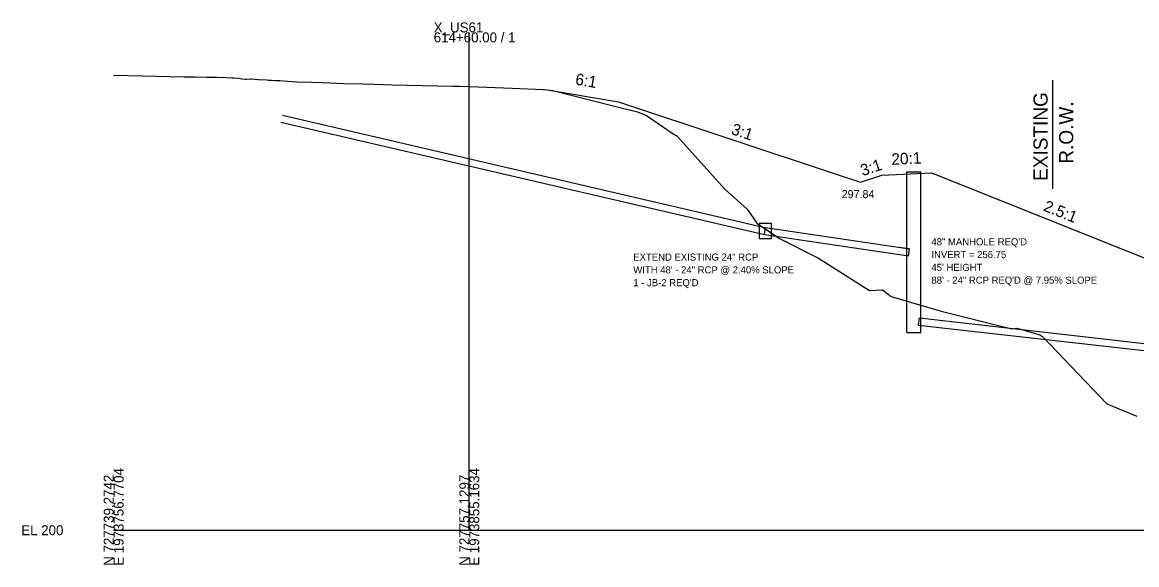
# Model space of a CAD drawing. Extents: x -26 to 1604, y -13 to 9623.
# Drawn here: x -25.7 to 287.7, y 6490.3 to 6642.8 of the extents above; entities that cross this region are included whole.
import ezdxf

# ---------------------------------------------------------------- set-up
doc = ezdxf.new("R2010")
doc.units = 0
for name, color, linetype in [('Draft_XS_Grid', 7, 'Continuous'), ('DTM_X_GROUND', 7, 'Continuous'), ('SLOPE_STAKES_FILL', 7, 'Continuous'), ('XS_CELL', 7, 'Continuous'), ('XS_P_DRAINAGE', 7, 'Continuous'), ('XS_P_GROUND', 7, 'Continuous'), ('XS_P_TX_DCH', 7, 'Continuous'), ('XS_P_TX_FS_BS', 7, 'Continuous'), ('XS_X_DRAINAGE', 7, 'Continuous'), ('XS_X_ROW', 7, 'Continuous')]:
    doc.layers.add(name, color=color, linetype=linetype)

msp = doc.modelspace()

# ---------------------------------------------------------------- linework, layer by layer
at = {"layer": 'DTM_X_GROUND'}
msp.add_lwpolyline([(0, 6628.01), (8.12, 6627.8), (19.86, 6627.49), (23.06, 6627.52), (26.15, 6627.45), (27.77, 6627.41), (29.12, 6627.38), (31.61, 6627.31), (33.25, 6627.26), (33.84, 6627.22), (33.93, 6627.21), (35.06, 6627.13), (36.06, 6626.94), (36.99, 6626.85), (37.37, 6626.83), (38.35, 6626.92), (38.76, 6626.9), (40.66, 6626.78), (40.95, 6626.76), (43.04, 6626.64), (43.52, 6626.61), (44.35, 6626.53), (45.53, 6626.48), (46.53, 6626.45), (46.71, 6626.45), (48.87, 6626.3), (48.89, 6626.29), (51.47, 6626.12), (51.53, 6626.11), (55.63, 6626.02), (58.82, 6625.89), (60.87, 6625.8), (64.73, 6625.66), (70.2, 6625.53), (73.2, 6625.43), (78.22, 6625.27), (95.43, 6624.92), (96.67, 6624.89), (97.24, 6624.88), (100.13, 6624.83), (112.07, 6624.34), (120.8, 6623.98), (121.11, 6623.95), (123.5, 6623.67), (140.87, 6619.3), (147.28, 6617.69), (149.84, 6616.66), (157.37, 6611.43), (158.34, 6610.95), (171.87, 6595.95), (178.1, 6590.33), (180.88, 6586.36), (187.21, 6582.01), (197.87, 6576.71), (198.06, 6576.61), (198.09, 6576.58), (198.13, 6576.56), (198.22, 6576.5), (212.5, 6567.45), (216.09, 6567.57), (216.16, 6567.57), (218.61, 6565.72), (232.66, 6561.62), (252.53, 6556.63), (253.95, 6556.86), (257.88, 6555.68), (260.43, 6554.98), (261.26, 6554.35), (279.32, 6535.56), (287.76, 6532.1)], dxfattribs=at)
at = {"layer": 'XS_CELL'}
for p, q in [((100, 6500), (100, 6640)), ((0, 6500), (100, 6500)), ((100, 6500), (600, 6500))]:
    msp.add_line(p, q, dxfattribs=at)
at = {"layer": 'XS_P_DRAINAGE'}
for p, q in [((223, 6555.65), (223, 6600.75)), ((223, 6600.75), (227, 6600.75)), ((227, 6555.65), (227, 6600.75)), ((183, 6583.12), (183.29, 6585.1)), ((183.29, 6585.1), (223.8, 6579.11)), ((183, 6583.12), (223.51, 6577.13)), ((223.8, 6579.11), (220.98, 6579.53)), ((223.51, 6577.13), (223.8, 6579.11)), ((226.36, 6557.7), (226.59, 6559.69)), ((226.59, 6559.69), (310.7, 6550.14)), ((226.36, 6557.7), (310.47, 6548.15)), ((223, 6555.65), (227, 6555.65))]:
    msp.add_line(p, q, dxfattribs=at)
msp.add_lwpolyline([(181.51, 6582.02), (184.98, 6582.02), (184.98, 6586.27), (181.51, 6586.27)], close=True, dxfattribs=at)
at = {"layer": 'XS_P_GROUND'}
for points in [[(122, 6623.84), (142, 6620.51)], [(142, 6620.51), (204, 6599.84), (210, 6597.84), (216, 6599.84), (230, 6600.54), (294, 6574.94), (300, 6572.54), (306, 6574.94), (320, 6575.64), (384, 6550.04), (390, 6547.64), (396, 6550.04), (410, 6550.74), (500.66, 6514.48)]]:
    msp.add_lwpolyline(points, dxfattribs=at)
at = {"layer": 'XS_X_DRAINAGE'}
for p, q in [((47.45, 6616.71), (183.45, 6585.07)), ((47, 6614.76), (183, 6583.12))]:
    msp.add_line(p, q, dxfattribs=at)
at = {"layer": 'XS_X_ROW'}
msp.add_line((264, 6626.53), (264, 6595.99), dxfattribs=at)

# ---------------------------------------------------------------- texts
at = {"layer": 'Draft_XS_Grid'}
msp.add_text('-', height=0.0001, dxfattribs=at).set_placement((0, 6500))
at = {"layer": 'SLOPE_STAKES_FILL'}
for p in [(141.96, 6620.45), (203.96, 6599.78), (215.96, 6599.78), (229.96, 6600.48), (209.96, 6597.78)]:
    msp.add_text('X', height=0.12, dxfattribs=at).set_placement(p)
at = {"layer": 'XS_CELL'}
for s, p in [('X_US61', (90, 6640)), ('614+60.00 / 1', (90, 6637.2)), ('EL 200', (-26, 6498.6))]:
    msp.add_text(s, height=2.8, dxfattribs=at).set_placement(p)
for s, p in [('N 727739.2742', (0, 6490)), ('E 1973756.7704', (2.8, 6490)), ('N 727757.1297', (100, 6490)), ('E 1973855.1634', (102.8, 6490))]:
    msp.add_text(s, height=2.8, rotation=90, dxfattribs=at).set_placement(p)
at = {"layer": 'XS_P_DRAINAGE'}
for s, p in [('48" MANHOLE REQ\'D', (229.95, 6580.12)), ('EXTEND EXISTING 24" RCP', (146.12, 6575.82)), ('INVERT = 256.75', (229.95, 6576.52)), ("45' HEIGHT", (229.95, 6572.92)), ('WITH 48\' - 24" RCP @ 2.40% SLOPE', (146.12, 6572.22)), ('88\' - 24" RCP REQ\'D @ 7.95% SLOPE', (229.95, 6569.32)), ("1 - JB-2 REQ'D", (146.12, 6568.62))]:
    msp.add_text(s, height=2, dxfattribs=at).set_placement(p)
at = {"layer": 'XS_P_GROUND'}
msp.add_text('X', height=0.12, dxfattribs=at).set_placement((121.96, 6623.78))
at = {"layer": 'XS_P_TX_DCH'}
msp.add_text('297.84', height=2.25, dxfattribs=at).set_placement((204.72, 6593.4))
at = {"layer": 'XS_P_TX_FS_BS'}
for s, rotation, p in [('6:1', 350.5377, (129.64, 6625.33)), ('3:1', 341.5651, (173.42, 6611.46)), ('20:1', 2.8624, (218.78, 6602.72)), ('3:1', 18.4349, (210.61, 6599.55)), ('2.5:1', 338.1986, (261.21, 6589.93))]:
    msp.add_text(s, height=3.24, rotation=rotation, dxfattribs=at).set_placement(p)
at = {"layer": 'XS_X_ROW'}
for s, p in [('EXISTING', (262.64, 6598.23)), ('R.O.W.', (269.84, 6603.07))]:
    msp.add_text(s, height=4, rotation=90, dxfattribs=at).set_placement(p)

doc.saveas('drawing.dxf')
